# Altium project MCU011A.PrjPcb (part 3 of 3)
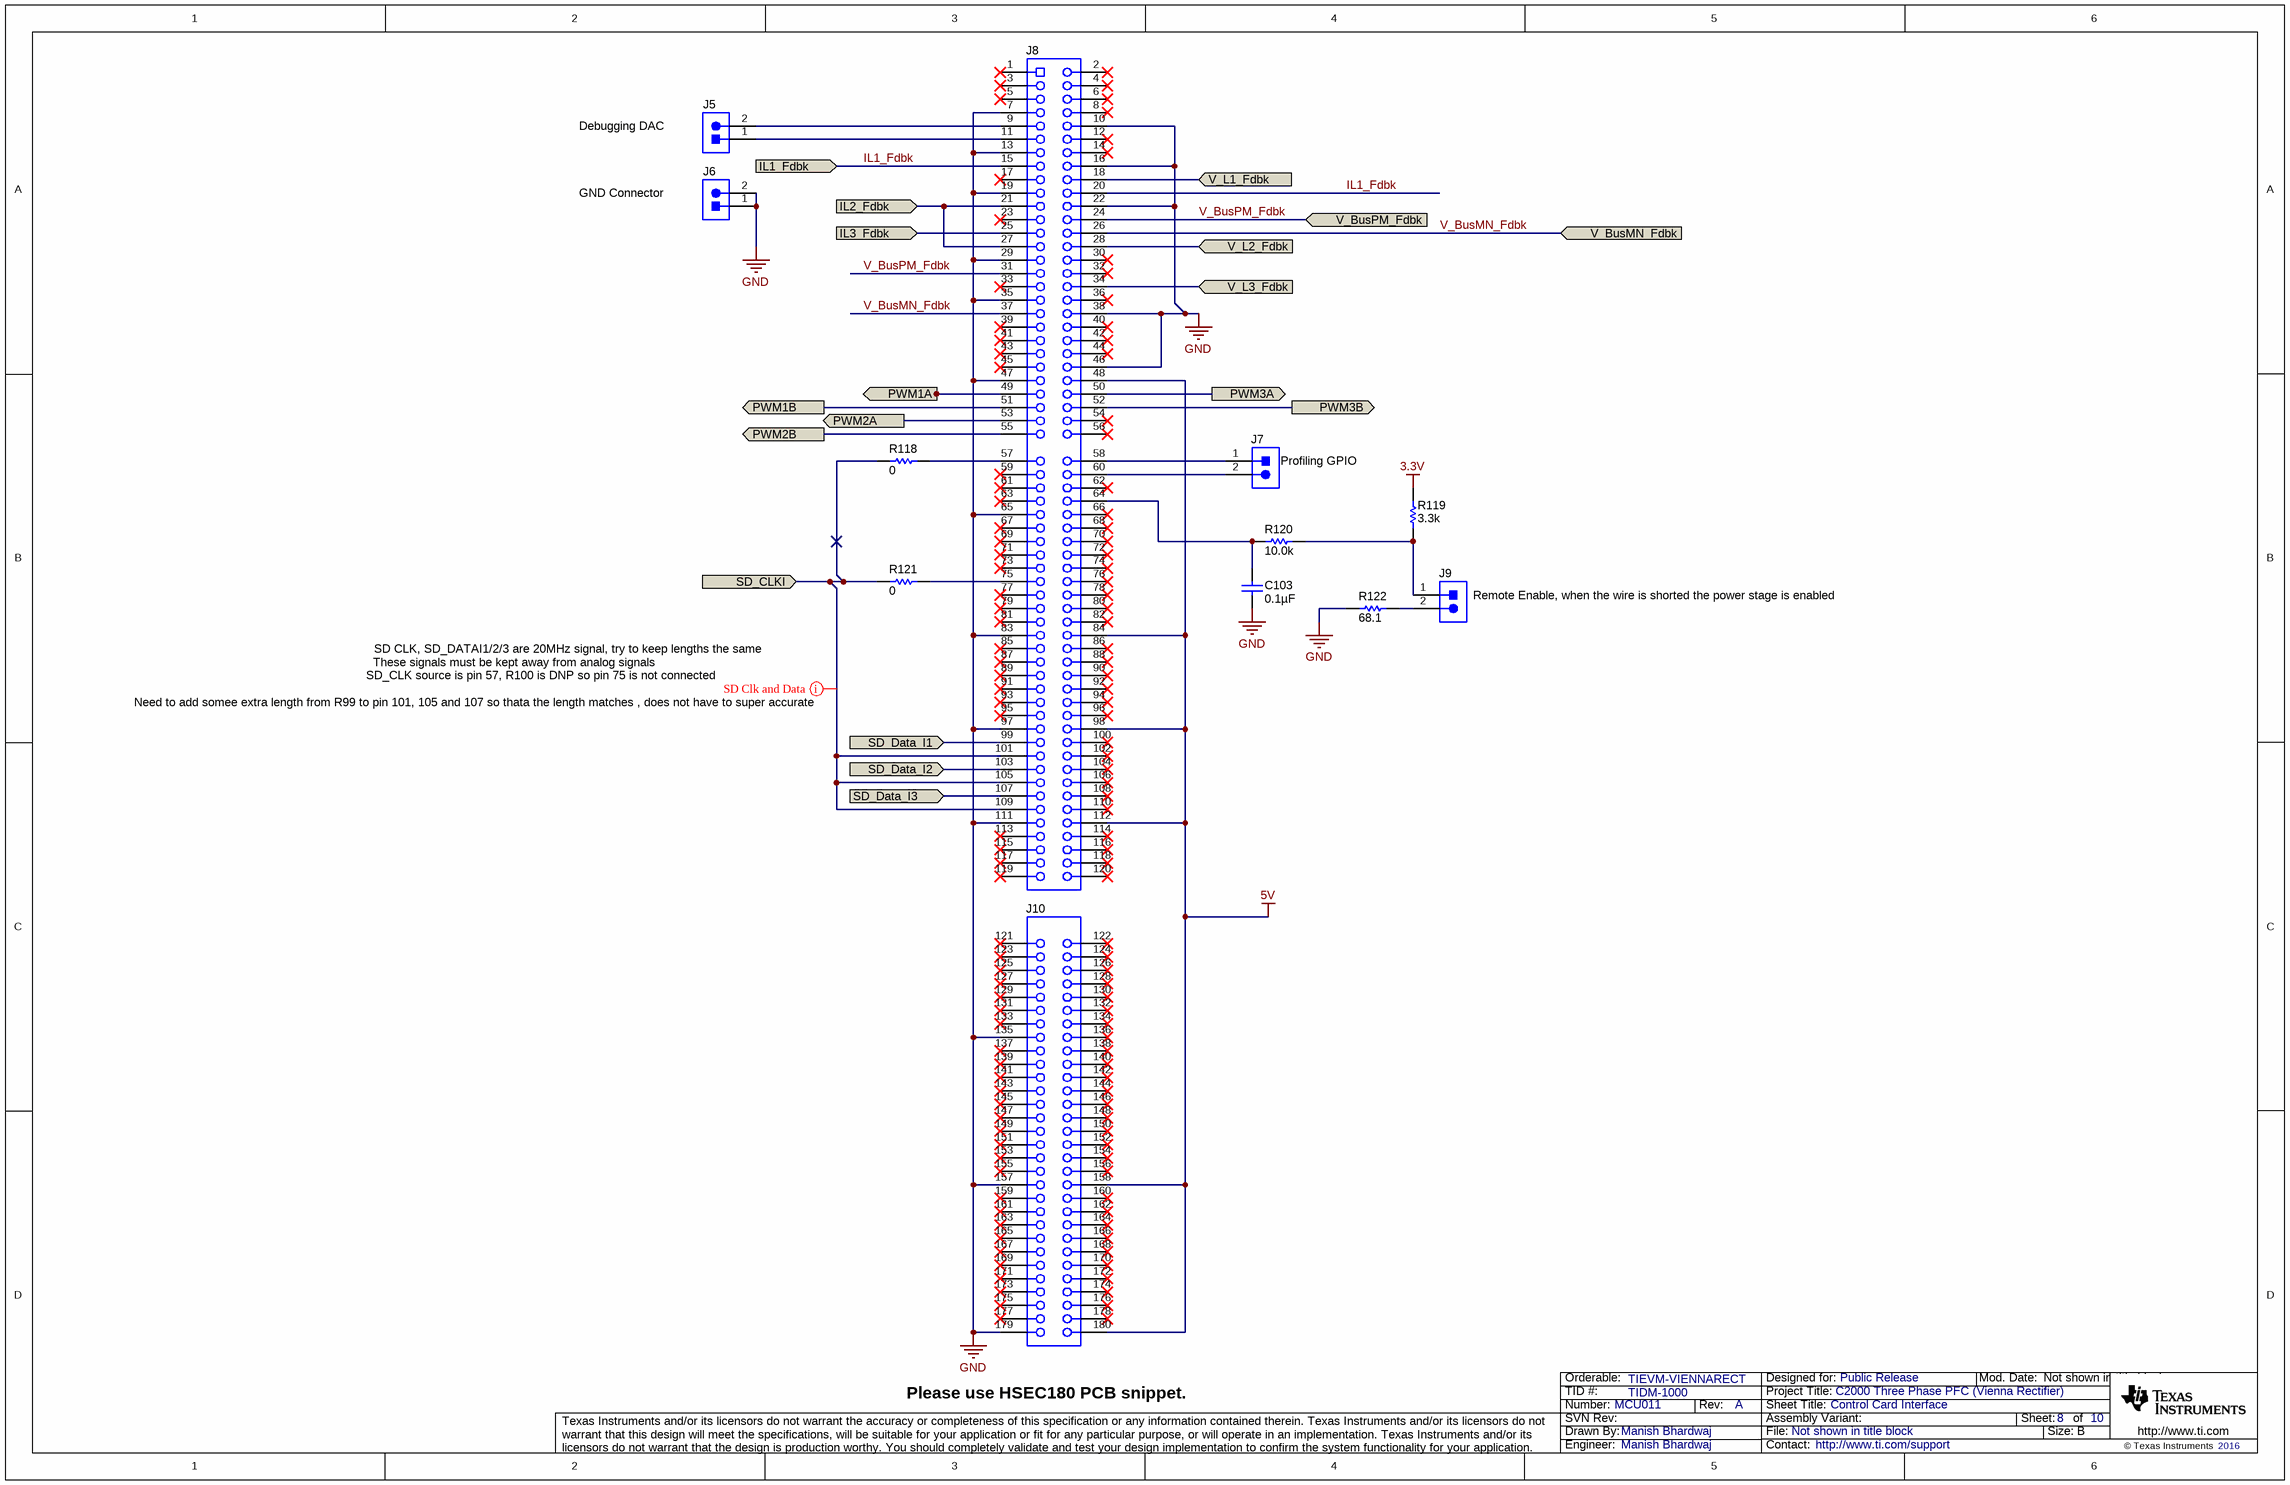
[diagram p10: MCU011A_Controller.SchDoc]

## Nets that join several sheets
3.3V: MCU011A_PWMDrivers (15 pins), MCU011A_ControllerPower (J12.2), MCU011A_SensingInductorCurrent (L9.2 L12.2 L13.2 L16.2), MCU011A_SensingInputVoltage (18 pins), MCU011A_SensingOutputVoltage (10 pins), MCU011A_Controller (R119.2)
5V: MCU011A_PowerStage (L1.2 L3.2 L6.2), MCU011A_ControllerPower (C111.1 J11.2 U31.3), MCU011A_SensingInductorCurrent (6 pins), MCU011A_SensingInputVoltage (C53.1 L7.1), MCU011A_SensingOutputVoltage (C91.1 L19.1), MCU011A_Controller (6 pins)
12V: MCU011A_CoverSheet (J4.1 U1.5), MCU011A_PWMDrivers (6 pins), MCU011A_ControllerPower (C104.1 L21.2)
GND: MCU011A_CoverSheet (J4.2 U1.7), MCU011A_PowerStage (12 pins), MCU011A_PWMDrivers (25 pins), MCU011A_ControllerPower (12 pins), MCU011A_SensingInductorCurrent (30 pins), MCU011A_SensingInputVoltage (32 pins), MCU011A_SensingOutputVoltage (18 pins), MCU011A_Controller (22 pins)
IL1_Fdbk: MCU011A_SensingInductorCurrent (C75.2 R88.2 TP_IL2.1), MCU011A_Controller (J8.15 J8.20)
IL1_N: MCU011A_PowerStage (R2.1), MCU011A_SensingInductorCurrent (R86.1 U22.6)
IL1_P: MCU011A_PowerStage (R1.2), MCU011A_SensingInductorCurrent (R90.2 U22.5)
IL2_Fdbk: MCU011A_SensingInductorCurrent (C74.2 R87.2 TP_IL1.1), MCU011A_Controller (J8.21 J8.27)
IL2_N: MCU011A_PowerStage (R10.1), MCU011A_SensingInductorCurrent (R85.1 U22.2)
IL2_P: MCU011A_PowerStage (R9.2), MCU011A_SensingInductorCurrent (R89.2 U22.3)
IL3_Fdbk: MCU011A_SensingInductorCurrent (C78.2 R92.1 TP_IL3.1), MCU011A_Controller (J8.25)
IL3_N: MCU011A_PowerStage (R18.1), MCU011A_SensingInductorCurrent (R91.1 U22.13)
IL3_P: MCU011A_PowerStage (R17.2), MCU011A_SensingInductorCurrent (R93.2 U22.12)
PWM1A: MCU011A_PWMDrivers (R22.2 TP1.1 U5.1), MCU011A_Controller (J8.49)
PWM1B: MCU011A_PWMDrivers (R23.2 TP2.1 U5.2), MCU011A_Controller (J8.51)
PWM2A: MCU011A_PWMDrivers (R41.2 TP5.1 U8.1), MCU011A_Controller (J8.53)
PWM2B: MCU011A_PWMDrivers (R39.2 TP6.1 U8.2), MCU011A_Controller (J8.55)
PWM3A: MCU011A_PWMDrivers (R31.2 TP3.1 U7.1), MCU011A_Controller (J8.50)
PWM3B: MCU011A_PWMDrivers (R32.2 TP4.1 U7.2), MCU011A_Controller (J8.52)
Q1_Gate: MCU011A_PowerStage (Q1.1), MCU011A_PWMDrivers (R19.1 R20.2 R21.2)
Q1_Source: MCU011A_PowerStage (Q1.3 Q2.3), MCU011A_PWMDrivers (8 pins)
Q2_Gate: MCU011A_PowerStage (Q2.1), MCU011A_PWMDrivers (R25.1 R26.2 R27.2)
Q3_Gate: MCU011A_PowerStage (Q3.1), MCU011A_PWMDrivers (R34.1 R35.2 R37.2)
Q3_Source: MCU011A_PowerStage (Q3.3 Q4.3), MCU011A_PWMDrivers (8 pins)
Q4_Gate: MCU011A_PowerStage (Q4.1), MCU011A_PWMDrivers (R43.1 R44.2 R45.2)
Q5_Gate: MCU011A_PowerStage (Q5.1), MCU011A_PWMDrivers (R28.1 R29.2 R30.2)
Q5_Source: MCU011A_PowerStage (Q5.3 Q6.3), MCU011A_PWMDrivers (8 pins)
Q6_Gate: MCU011A_PowerStage (Q6.1), MCU011A_PWMDrivers (R36.1 R38.2 R40.2)
RSH1_1: MCU011A_PowerStage (RSH1.1 U2.4), MCU011A_SensingInductorCurrent (U19.2)
RSH1_2: MCU011A_PowerStage (L2.1 RSH1.2), MCU011A_SensingInductorCurrent (6 pins)
RSH2_1: MCU011A_PowerStage (RSH2.1 U3.4), MCU011A_SensingInductorCurrent (U21.2)
RSH2_2: MCU011A_PowerStage (L4.1 RSH2.2), MCU011A_SensingInductorCurrent (6 pins)
RSH3_1: MCU011A_PowerStage (RSH3.1 U4.4), MCU011A_SensingInductorCurrent (U24.2)
RSH3_2: MCU011A_PowerStage (L5.1 RSH3.2), MCU011A_SensingInductorCurrent (6 pins)
SD_CLKI: MCU011A_SensingInductorCurrent (TP_SD_CLKI1.1 U19.13 U21.13 U24.13), MCU011A_Controller (5 pins)
SD_Data_I1: MCU011A_SensingInductorCurrent (TP_SD_DATA_1.1 U19.11), MCU011A_Controller (J8.99)
SD_Data_I2: MCU011A_SensingInductorCurrent (TP_SD_DATA_2.1 U21.11), MCU011A_Controller (J8.103)
SD_Data_I3: MCU011A_SensingInductorCurrent (TP_SD_DATA_3.1 U24.11), MCU011A_Controller (J8.107)
V_A: MCU011A_PowerStage (U2.1 U2.2), MCU011A_EMCInputFilter (Cvn3.1 Cvn6.1 Lcm2.1 Rvn3.2), MCU011A_SensingInputVoltage (R46.2)
V_B: MCU011A_PowerStage (U3.1 U3.2), MCU011A_EMCInputFilter (Cvn2.1 Cvn5.1 Lcm2.3 Rvn2.2), MCU011A_SensingInputVoltage (R61.2)
V_BusMN_Fdbk: MCU011A_SensingOutputVoltage (C100.1 R113.2 TP_VBUSMN_Fdbk1.1), MCU011A_Controller (J8.26 J8.37)
V_BusPM_Fdbk: MCU011A_SensingOutputVoltage (C88.2 R101.2 TP_VBUSPM_Fdbk1.1), MCU011A_Controller (J8.24 J8.31)
V_C: MCU011A_PowerStage (U4.1 U4.2), MCU011A_EMCInputFilter (Cvn1.1 Cvn4.1 Lcm2.5 Rvn1.2), MCU011A_SensingInputVoltage (R73.2)
V_Earth: MCU011A_CoverSheet (J3.2), MCU011A_EMCInputFilter (Cy1.2 Cy2.2 Cy3.2 TP_E1.1)
V_L1: MCU011A_CoverSheet (J2.1), MCU011A_EMCInputFilter (TP_VL1.1 XF1.2)
V_L1_Fdbk: MCU011A_SensingInputVoltage (C33.1 R53.2 TP_VL1_Fdbk.1), MCU011A_Controller (J8.18)
V_L2: MCU011A_CoverSheet (J2.2), MCU011A_EMCInputFilter (TP_VL2.1 XF2.2)
V_L2_Fdbk: MCU011A_SensingInputVoltage (C45.2 R68.2 TP_VL2_Fdbk.1), MCU011A_Controller (J8.28)
V_L3: MCU011A_CoverSheet (J2.3), MCU011A_EMCInputFilter (TP_VL3.1 XF3.2)
V_L3_Fdbk: MCU011A_SensingInputVoltage (C58.1 R80.2 TP_VL3_Fdbk.1), MCU011A_Controller (J8.34)
V_M: MCU011A_CoverSheet (C1.1 J1.2 U1.1), MCU011A_PowerStage (18 pins), MCU011A_EMCInputFilter (Cm1.2), MCU011A_SensingOutputVoltage (13 pins)
V_N_Meas: MCU011A_CoverSheet (J3.1), MCU011A_EMCInputFilter (8 pins), MCU011A_SensingInputVoltage (18 pins)
VBUSN: MCU011A_CoverSheet (C1.2 J1.1 U1.2 U1.4), MCU011A_PowerStage (11 pins), MCU011A_SensingOutputVoltage (R106.2)
VBUSP: MCU011A_CoverSheet (J1.3), MCU011A_PowerStage (11 pins), MCU011A_SensingOutputVoltage (R94.2)

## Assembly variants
001: not fitted C26 C31 C34 C35 C39 C44 C46 C47 C49 C57 C59 C60 C82 C87 C89 C90 C94 C99 C101 C102 Cm1 FID1 FID2 FID3 FID4 FID5 FID6 R118 U1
